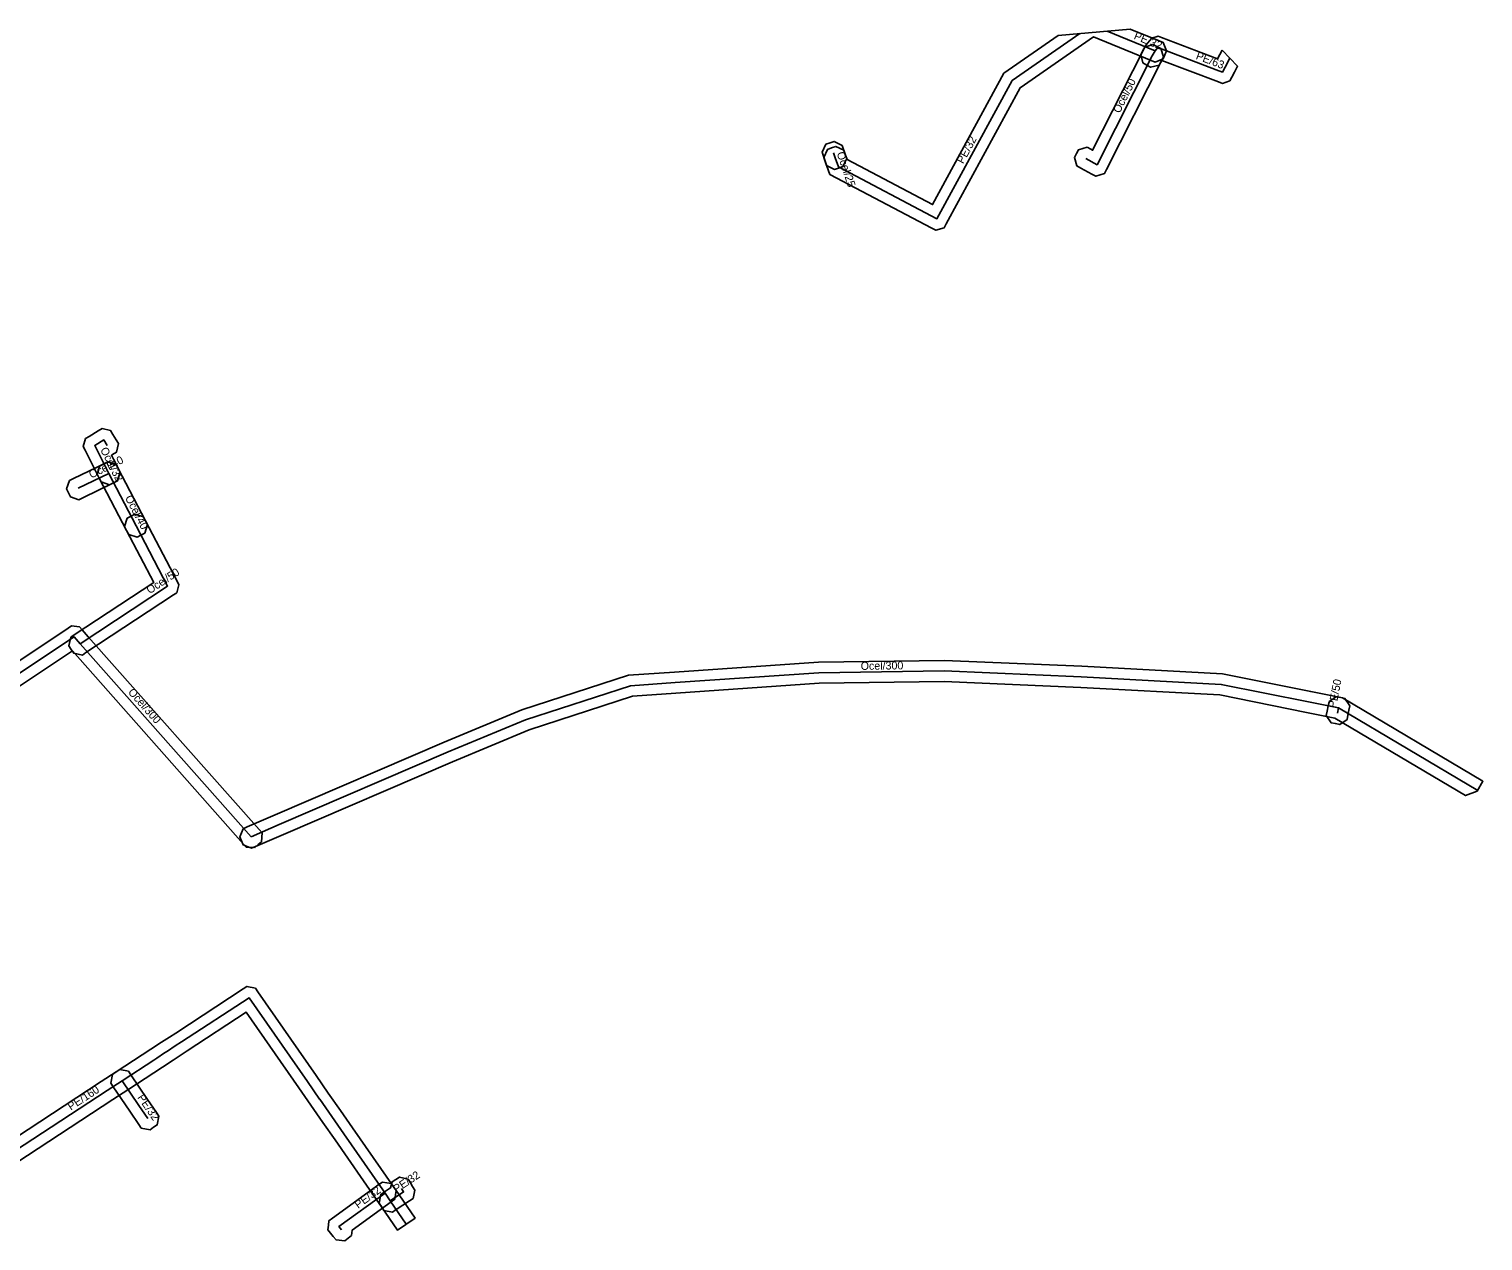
# Model space of a CAD drawing. Extents: x -492768 to -492424, y -1126490 to -1126252.
# Drawn here: x -492560.8 to -492424, y -1126366.5 to -1126252.4 of the extents above; entities that cross this region are included whole.
import ezdxf

# ---------------------------------------------------------------- set-up
doc = ezdxf.new("R2010")
doc.units = 0
for name, color, linetype in [('1', 7, 'Continuous'), ('14', 7, 'Continuous'), ('20', 7, 'Continuous'), ('24', 7, 'Continuous'), ('30', 7, 'Continuous')]:
    doc.layers.add(name, color=color, linetype=linetype)

msp = doc.modelspace()

# ---------------------------------------------------------------- linework, layer by layer
at = {"layer": '1'}
for points in [[(-492463.93, -1126252.99), (-492457.17, -1126252.39), (-492454.44, -1126253.51), (-492454.06, -1126253.66), (-492453.74, -1126254.43), (-492453.9, -1126254.81), (-492454.05, -1126255.19), (-492454.82, -1126255.51), (-492455.2, -1126255.35), (-492460.63, -1126253.13), (-492467.53, -1126257.92), (-492474.48, -1126270.73), (-492474.68, -1126271.09), (-492475.46, -1126271.33), (-492475.83, -1126271.14), (-492485.43, -1126266.07), (-492485.87, -1126264.86), (-492486.01, -1126264.47), (-492485.66, -1126263.72), (-492485.27, -1126263.58), (-492484.88, -1126263.44), (-492484.13, -1126263.79), (-492483.99, -1126264.18), (-492483.81, -1126264.67), (-492475.77, -1126268.91), (-492469.05, -1126256.54)], [(-492461.23, -1126263.51), (-492460.86, -1126263.71), (-492460.71, -1126263.79), (-492455.99, -1126254.47), (-492455.8, -1126254.1), (-492455.02, -1126253.84), (-492454.65, -1126254.03), (-492454.28, -1126254.22), (-492454.02, -1126255), (-492454.21, -1126255.37), (-492459.39, -1126265.61), (-492459.58, -1126265.99), (-492459.98, -1126266.11), (-492460.39, -1126266.24), (-492460.76, -1126266.04), (-492461.81, -1126265.47), (-492462.18, -1126265.27), (-492462.41, -1126264.48), (-492462.22, -1126264.11), (-492462.02, -1126263.75)], [(-492448.51, -1126254.37), (-492447.05, -1126255.89), (-492447.35, -1126256.44), (-492447.61, -1126256.92), (-492447.79, -1126257.25), (-492448.49, -1126257.51), (-492448.85, -1126257.37), (-492454.19, -1126255.34), (-492454.23, -1126255.42), (-492454.44, -1126255.78), (-492455.24, -1126255.99), (-492455.6, -1126255.79), (-492455.96, -1126255.58), (-492456.17, -1126254.78), (-492455.97, -1126254.42), (-492455.65, -1126253.86), (-492455.35, -1126253.49), (-492455.14, -1126253.24), (-492454.52, -1126253.07), (-492454.21, -1126253.19), (-492448.95, -1126255.19)], [(-492484.28, -1126263.34), (-492484.14, -1126263.73), (-492483.98, -1126264.2), (-492483.85, -1126264.59), (-492484.22, -1126265.33), (-492484.61, -1126265.47), (-492485, -1126265.6), (-492485.74, -1126265.23), (-492485.88, -1126264.84), (-492486.04, -1126264.37), (-492486.17, -1126263.98), (-492485.8, -1126263.24), (-492485.41, -1126263.1), (-492485.02, -1126262.97)], [(-492552.96, -1126292.44), (-492553.06, -1126292.51), (-492552.43, -1126293.77), (-492552.24, -1126294.14), (-492552.5, -1126294.92), (-492552.87, -1126295.11), (-492553.24, -1126295.29), (-492554.03, -1126295.03), (-492554.22, -1126294.67), (-492555.54, -1126292.04), (-492555.71, -1126291.69), (-492555.49, -1126290.94), (-492555.16, -1126290.74), (-492554.3, -1126290.22), (-492553.95, -1126290), (-492553.15, -1126290.2), (-492552.93, -1126290.56), (-492552.62, -1126291.07), (-492552.41, -1126291.42), (-492552.6, -1126292.23)], [(-492557.01, -1126294.9), (-492556.64, -1126294.72), (-492553.76, -1126293.32), (-492553.39, -1126293.14), (-492552.6, -1126293.4), (-492552.42, -1126293.78), (-492552.24, -1126294.15), (-492552.51, -1126294.93), (-492552.88, -1126295.11), (-492555.76, -1126296.52), (-492556.13, -1126296.7), (-492556.92, -1126296.43), (-492557.1, -1126296.06), (-492557.28, -1126295.69)], [(-492552.63, -1126293.39), (-492552.43, -1126293.75), (-492549.86, -1126298.68), (-492549.67, -1126299.05), (-492549.92, -1126299.84), (-492550.29, -1126300.03), (-492550.65, -1126300.22), (-492551.44, -1126299.98), (-492551.64, -1126299.61), (-492554.21, -1126294.68), (-492554.4, -1126294.31), (-492554.15, -1126293.52), (-492553.79, -1126293.33), (-492553.42, -1126293.14)], [(-492550.05, -1126298.32), (-492549.86, -1126298.68), (-492546.89, -1126304.37), (-492546.72, -1126304.71), (-492546.91, -1126305.46), (-492547.23, -1126305.67), (-492555.46, -1126311.1), (-492555.8, -1126311.33), (-492556.61, -1126311.16), (-492556.84, -1126310.82), (-492557.07, -1126310.47), (-492556.9, -1126309.66), (-492556.56, -1126309.43), (-492549.08, -1126304.5), (-492551.64, -1126299.61), (-492551.83, -1126299.24), (-492551.58, -1126298.45), (-492551.21, -1126298.26), (-492550.85, -1126298.07)], [(-492540.65, -1126329.1), (-492556.74, -1126310.94), (-492560.59, -1126313.5), (-492564.77, -1126316.28), (-492565.11, -1126316.51), (-492565.93, -1126316.34), (-492566.16, -1126316), (-492566.38, -1126315.66), (-492566.22, -1126314.84), (-492565.88, -1126314.61), (-492561.7, -1126311.83), (-492557.13, -1126308.79), (-492556.82, -1126308.59), (-492556.07, -1126308.68), (-492555.83, -1126308.96), (-492555.26, -1126309.6), (-492539.15, -1126327.77), (-492538.88, -1126328.08), (-492538.93, -1126328.91), (-492539.24, -1126329.18), (-492539.55, -1126329.46), (-492540.37, -1126329.41)], [(-492424.49, -1126324.15), (-492425.6, -1126324.56), (-492437.91, -1126317.26), (-492440.57, -1126316.73), (-492448.72, -1126315.09), (-492461.82, -1126314.39), (-492474.68, -1126313.83), (-492486.44, -1126313.99), (-492499.93, -1126314.93), (-492504, -1126315.21), (-492513.73, -1126318.37), (-492520.96, -1126321.37), (-492536.86, -1126328.22), (-492539.5, -1126329.35), (-492539.88, -1126329.52), (-492540.65, -1126329.21), (-492540.82, -1126328.83), (-492540.98, -1126328.45), (-492540.67, -1126327.68), (-492540.29, -1126327.52), (-492537.66, -1126326.38), (-492521.74, -1126319.53), (-492514.43, -1126316.49), (-492504.38, -1126313.23), (-492500.07, -1126312.93), (-492486.52, -1126311.99), (-492474.66, -1126311.83), (-492461.72, -1126312.39), (-492448.46, -1126313.1), (-492440.17, -1126314.77), (-492437.18, -1126315.37), (-492423.96, -1126323.21)], [(-492438.71, -1126317.02), (-492438.63, -1126316.61), (-492438.53, -1126316.12), (-492438.45, -1126315.71), (-492437.76, -1126315.25), (-492437.35, -1126315.33), (-492436.95, -1126315.42), (-492436.49, -1126316.1), (-492436.57, -1126316.51), (-492436.67, -1126317), (-492436.75, -1126317.41), (-492437.44, -1126317.87), (-492437.84, -1126317.79), (-492438.25, -1126317.7)], [(-492551.47, -1126350.52), (-492551.23, -1126350.86), (-492549.66, -1126353.17), (-492548.82, -1126354.41), (-492548.59, -1126354.75), (-492548.75, -1126355.57), (-492549.09, -1126355.8), (-492549.43, -1126356.03), (-492550.25, -1126355.87), (-492550.48, -1126355.53), (-492551.32, -1126354.29), (-492552.89, -1126351.98), (-492553.12, -1126351.64), (-492552.97, -1126350.83), (-492552.62, -1126350.59), (-492552.28, -1126350.36)], [(-492526.72, -1126362.81), (-492530.4, -1126365.48), (-492530.45, -1126365.98), (-492530.77, -1126366.24), (-492531.1, -1126366.5), (-492531.92, -1126366.41), (-492532.18, -1126366.09), (-492532.43, -1126365.78), (-492532.7, -1126365.44), (-492532.64, -1126365.02), (-492532.59, -1126364.59), (-492532.24, -1126364.34), (-492527.9, -1126361.19), (-492527.56, -1126360.95), (-492526.74, -1126361.08), (-492526.5, -1126361.41), (-492526.26, -1126361.75), (-492526.39, -1126362.57)], [(-492527.36, -1126361.89), (-492526.79, -1126361.5), (-492526.65, -1126360.92), (-492526.29, -1126360.7), (-492525.94, -1126360.48), (-492525.14, -1126360.67), (-492524.92, -1126361.03), (-492524.71, -1126361.36), (-492524.5, -1126361.71), (-492524.67, -1126362.5), (-492525.01, -1126362.72), (-492526.26, -1126363.55), (-492526.6, -1126363.78), (-492527.41, -1126363.62), (-492527.64, -1126363.27), (-492527.87, -1126362.93), (-492527.71, -1126362.12)]]:
    msp.add_lwpolyline(points, close=True, dxfattribs=at)
msp.add_lwpolyline([(-492566.7, -1126359.79), (-492554.02, -1126351.5), (-492552.61, -1126350.58), (-492549.35, -1126348.45), (-492548.35, -1126347.79), (-492547.59, -1126347.3), (-492547, -1126346.92), (-492540.65, -1126342.76), (-492540.31, -1126342.54), (-492539.51, -1126342.7), (-492539.28, -1126343.03), (-492533.79, -1126350.93), (-492532.65, -1126352.57), (-492531.51, -1126354.21), (-492530.37, -1126355.85), (-492526.49, -1126361.43), (-492525.99, -1126362.15), (-492524.48, -1126364.35), (-492526.15, -1126365.47), (-492527.63, -1126363.29), (-492528.13, -1126362.57), (-492532.01, -1126356.99), (-492533.15, -1126355.35), (-492534.29, -1126353.71), (-492535.43, -1126352.07), (-492540.37, -1126344.97), (-492545.92, -1126348.6), (-492546.51, -1126348.98), (-492547.25, -1126349.47), (-492548.25, -1126350.13), (-492551.51, -1126352.26), (-492552.92, -1126353.18), (-492566.03, -1126361.74)], dxfattribs=at)
at = {"layer": '14'}
for points in [[(-492553.48, -1126291.59), (-492553.79, -1126291.07), (-492554.64, -1126291.59), (-492553.32, -1126294.22)], [(-492556.2, -1126295.62), (-492553.32, -1126294.22)], [(-492553.32, -1126294.22), (-492550.75, -1126299.15)], [(-492550.75, -1126299.15), (-492547.78, -1126304.83), (-492556.01, -1126310.27)], [(-492539.9, -1126328.44), (-492556.01, -1126310.27), (-492556.57, -1126309.63), (-492561.14, -1126312.67), (-492565.32, -1126315.45)], [(-492539.9, -1126328.44), (-492537.26, -1126327.3), (-492521.35, -1126320.45), (-492514.08, -1126317.43), (-492504.19, -1126314.22), (-492500, -1126313.93), (-492486.48, -1126312.99), (-492474.67, -1126312.83), (-492461.77, -1126313.39), (-492448.59, -1126314.1), (-492440.37, -1126315.75), (-492437.55, -1126316.31), (-492424.45, -1126324.08)], [(-492437.65, -1126316.8), (-492437.55, -1126316.31)]]:
    msp.add_lwpolyline(points, dxfattribs=at)
at = {"layer": '24'}
for points in [[(-492484.93, -1126264.52), (-492484.62, -1126265.37), (-492475.36, -1126270.25), (-492468.29, -1126257.23), (-492461.92, -1126252.81)], [(-492459.34, -1126252.58), (-492454.82, -1126254.43)], [(-492455.1, -1126254.92), (-492454.82, -1126254.43), (-492454.57, -1126254.12), (-492449.08, -1126256.22), (-492448.49, -1126256.44), (-492448.23, -1126255.96), (-492447.78, -1126255.13)], [(-492461.34, -1126264.59), (-492460.28, -1126265.16), (-492455.1, -1126254.92)], [(-492485.09, -1126264.05), (-492484.93, -1126264.52)], [(-492566.57, -1126360.9), (-492553.47, -1126352.34), (-492552.06, -1126351.42), (-492549.08, -1126349.47), (-492548.8, -1126349.29), (-492548.8, -1126349.29), (-492548.06, -1126348.8), (-492547.8, -1126348.63), (-492547.05, -1126348.14), (-492546.46, -1126347.76), (-492540.1, -1126343.6), (-492534.61, -1126351.5), (-492533.47, -1126353.14), (-492533.46, -1126353.15), (-492532.33, -1126354.78), (-492532.32, -1126354.79), (-492531.19, -1126356.42), (-492527.31, -1126362), (-492526.81, -1126362.72), (-492525.32, -1126364.91)], [(-492552.06, -1126351.42), (-492550.49, -1126353.73), (-492550.49, -1126353.73), (-492549.65, -1126354.97)], [(-492527.31, -1126362), (-492531.65, -1126365.15), (-492531.4, -1126365.46)], [(-492526.81, -1126362.72), (-492525.56, -1126361.89), (-492525.77, -1126361.55)]]:
    msp.add_lwpolyline(points, dxfattribs=at)

# ---------------------------------------------------------------- texts
at = {"layer": '20'}
for s, rotation, p in [('Ocel/32', 296.7134, (-492554.14, -1126291.99)), ('Ocel/40', 26.0206, (-492554.96, -1126294.72)), ('Ocel/40', 297.5556, (-492551.81, -1126296.52)), ('Ocel/50', 33.4337, (-492549.46, -1126305.61)), ('Ocel/300', 0.7762, (-492482.53, -1126312.73)), ('PE/50', 78.6901, (-492437.8, -1126316.36)), ('Ocel/300', 311.5557, (-492551.55, -1126314.86))]:
    msp.add_text(s, height=0.75, rotation=rotation, dxfattribs=at).set_placement(p)
at = {"layer": '30'}
for s, rotation, p in [('PE/32', 337.7171, (-492456.88, -1126253.3)), ('PE/63', 339.1165, (-492451.04, -1126255.19)), ('Ocel/50', 63.1603, (-492458.16, -1126260.37)), ('PE/32', 61.4976, (-492472.89, -1126265.13)), ('Ocel/25', 288.7999, (-492484.81, -1126264.08)), ('PE/160', 33.1663, (-492556.88, -1126354.24)), ('PE/32', 304.2089, (-492550.65, -1126352.99)), ('PE/32', 33.5842, (-492526.22, -1126361.99)), ('PE/32', 35.9724, (-492529.84, -1126363.49))]:
    msp.add_text(s, height=0.75, rotation=rotation, dxfattribs=at).set_placement(p)

doc.saveas('drawing.dxf')
